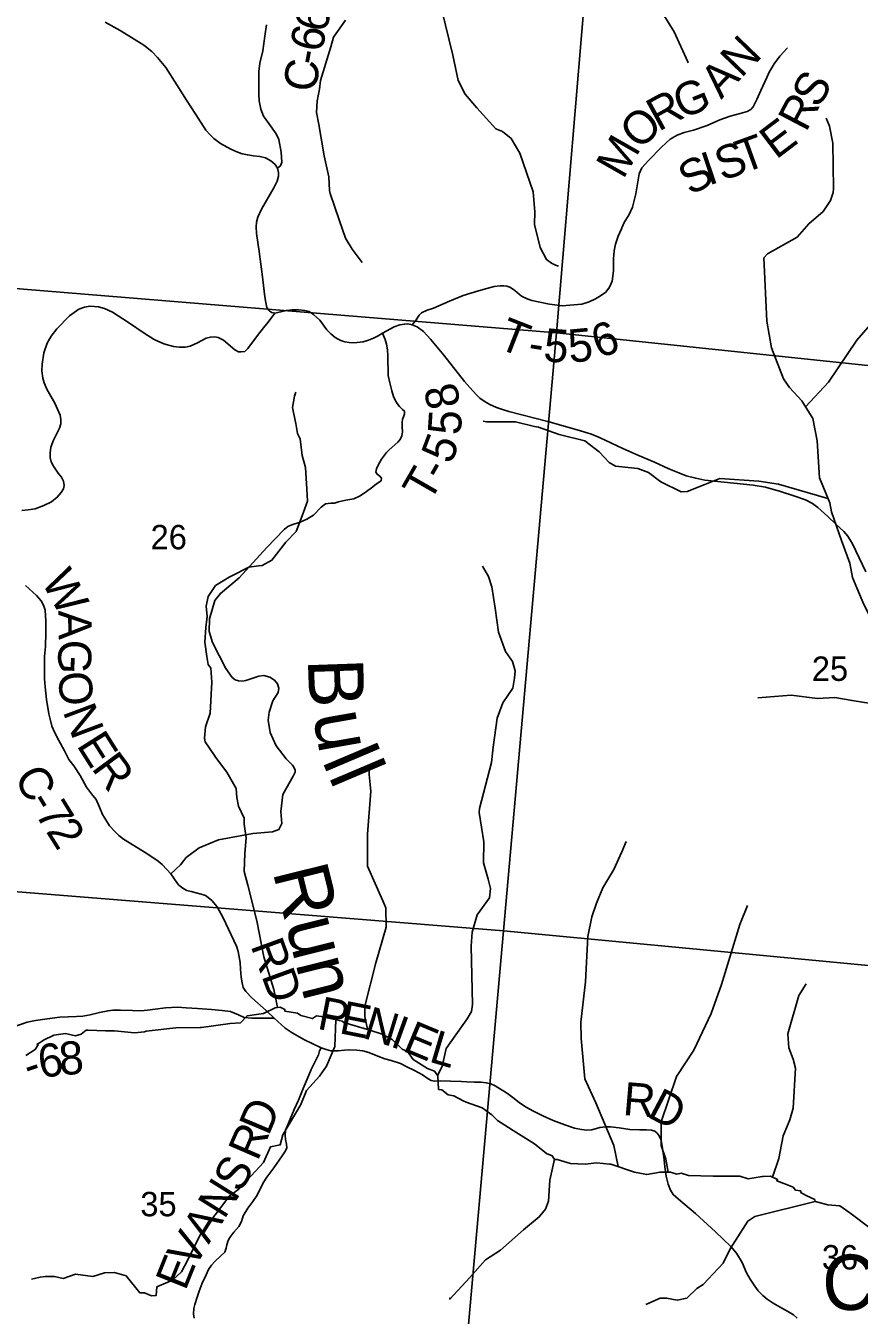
# Model space of a CAD drawing. Extents: x 1878108 to 2183446, y 146837 to 508383.
# Drawn here: x 1969519 to 1977068, y 283114 to 294796 of the extents above; entities that cross this region are included whole.
import ezdxf

# ---------------------------------------------------------------- set-up
doc = ezdxf.new("R2010")
doc.units = 0
for name, color, linetype in [('GM_X_County_Road', 7, 'Continuous'), ('GM_X_County_Road_Text', 7, 'Continuous'), ('GM_X_Minor_River', 7, 'Continuous'), ('GM_X_Minor_River_Text', 7, 'Continuous'), ('GM_X_Section', 7, 'Continuous'), ('GM_X_Section_Text', 7, 'Continuous'), ('GM_X_State_Route', 7, 'Continuous'), ('GM_X_Township_Road', 7, 'Continuous'), ('GM_X_Township_Road_Text', 7, 'Continuous'), ('GM_X_Township_ROW', 7, 'Continuous')]:
    doc.layers.add(name, color=color, linetype=linetype)

msp = doc.modelspace()

# ---------------------------------------------------------------- linework, layer by layer
at = {"layer": 'GM_X_County_Road'}
for points in [[(1971799, 293506), (1971825, 293529), (1971839, 293562), (1971832, 293651), (1971810, 293766), (1971787, 293817), (1971721, 293912), (1971672, 293979), (1971648, 294042), (1971633, 294115), (1971630, 294173), (1971629, 294275), (1971630, 294383), (1971639, 294459), (1971665, 294569), (1971684, 294701), (1971700, 294804)], [(1969483, 290405), (1969539, 290410), (1969603, 290420), (1969683, 290449), (1969750, 290483), (1969804, 290525), (1969840, 290567), (1969859, 290601), (1969865, 290632), (1969860, 290671), (1969841, 290708), (1969813, 290744), (1969769, 290806), (1969749, 290845), (1969739, 290885), (1969738, 290928), (1969744, 290978), (1969770, 291041), (1969824, 291152), (1969836, 291190), (1969837, 291230), (1969830, 291270), (1969782, 291377), (1969710, 291503), (1969686, 291561), (1969674, 291605), (1969665, 291669), (1969666, 291731), (1969681, 291834), (1969712, 291920), (1969747, 291984), (1969799, 292051), (1969915, 292168), (1969999, 292228), (1970050, 292247), (1970100, 292255), (1970178, 292249), (1970232, 292234), (1970305, 292202), (1970448, 292108), (1970591, 292010), (1970680, 291955), (1970770, 291914), (1970858, 291890), (1970910, 291884), (1970966, 291885), (1971008, 291895), (1971075, 291925), (1971154, 291965), (1971191, 291976), (1971231, 291979), (1971262, 291973), (1971309, 291948), (1971411, 291861), (1971445, 291843), (1971470, 291841), (1971502, 291846), (1971531, 291872), (1971618, 291991), (1971673, 292061), (1971715, 292110), (1971775, 292194)], [(1971769, 285804), (1971697, 285875), (1971565, 285990), (1971512, 286047), (1971488, 286084), (1971478, 286125), (1971469, 286176), (1971465, 286249), (1971459, 286310), (1971447, 286376), (1971442, 286409), (1971426, 286457), (1971306, 286715), (1971251, 286814), (1971203, 286870), (1971172, 286899), (1971147, 286917), (1971108, 286928), (1971016, 286952), (1970978, 286962), (1970950, 286978), (1970930, 286992), (1970905, 287009), (1970892, 287025), (1970859, 287074), (1970831, 287112), (1970795, 287153), (1970754, 287196), (1970717, 287227), (1970615, 287297), (1970404, 287426), (1970360, 287460), (1970324, 287497), (1970278, 287549), (1970243, 287602), (1970213, 287650), (1970186, 287716), (1970156, 287786), (1970114, 287837), (1970069, 287899), (1970010, 288004), (1969955, 288092), (1969909, 288149), (1969865, 288232), (1969819, 288320), (1969782, 288389), (1969753, 288452), (1969742, 288501), (1969728, 288563), (1969707, 288692), (1969694, 288807), (1969688, 288879), (1969689, 289000), (1969689, 289083), (1969696, 289173), (1969701, 289297), (1969700, 289403), (1969694, 289501), (1969679, 289546), (1969658, 289587), (1969615, 289634), (1969515, 289725)], [(1969410, 285726), (1969530, 285768), (1969607, 285784), (1969713, 285800), (1969826, 285813), (1969977, 285821), (1970035, 285823), (1970102, 285836), (1970185, 285856), (1970264, 285873), (1970308, 285877), (1970376, 285878), (1970484, 285875), (1970561, 285873), (1970622, 285877), (1970691, 285886), (1970785, 285900), (1970892, 285905), (1970971, 285900), (1971073, 285894), (1971202, 285884), (1971298, 285876), (1971373, 285864), (1971445, 285835), (1971497, 285812), (1971567, 285805), (1971640, 285804), (1971769, 285804), (1971869, 285715), (1971933, 285671), (1972042, 285610), (1972194, 285536), (1972239, 285521), (1972282, 285510), (1972317, 285508), (1972349, 285509), (1972406, 285516), (1972453, 285518), (1972518, 285515), (1972572, 285508), (1972625, 285493), (1972707, 285461), (1972771, 285437), (1972827, 285422), (1972912, 285394), (1972975, 285361), (1973034, 285335), (1973079, 285310), (1973112, 285292), (1973164, 285255), (1973192, 285240), (1973220, 285234), (1973274, 285236), (1973365, 285234), (1973465, 285230), (1973513, 285228), (1973582, 285225), (1973645, 285224), (1973689, 285220), (1973730, 285211), (1973769, 285192), (1973818, 285162), (1973850, 285144), (1973882, 285122), (1973932, 285085), (1973988, 285040), (1974037, 285007), (1974072, 284986), (1974124, 284959), (1974202, 284919), (1974295, 284879), (1974402, 284839), (1974490, 284808), (1974553, 284795), (1974602, 284791), (1974647, 284794), (1974720, 284813), (1974773, 284822), (1974814, 284821), (1974893, 284812), (1974990, 284797), (1975079, 284792), (1975142, 284792), (1975188, 284791), (1975216, 284781), (1975239, 284763), (1975256, 284739), (1975273, 284700), (1975287, 284623), (1975300, 284521), (1975308, 284459), (1975319, 284375), (1975338, 284300), (1975359, 284248), (1975382, 284207), (1975431, 284165), (1975586, 284036), (1975767, 283870), (1975905, 283735), (1975958, 283675), (1976009, 283590), (1976048, 283497), (1976081, 283439), (1976124, 283376), (1976153, 283336), (1976195, 283292), (1976233, 283259), (1976288, 283223), (1976373, 283175), (1976429, 283145), (1976474, 283116), (1976506, 283086)]]:
    msp.add_lwpolyline(points, dxfattribs=at)
at = {"layer": 'GM_X_Minor_River'}
for points in [[(1973941, 296117), (1974021, 296095), (1974173, 295826), (1974252, 295750), (1974320, 295711), (1974458, 295677), (1974544, 295619), (1974697, 295565), (1974867, 295436), (1975097, 295218), (1975140, 295140), (1975208, 295065), (1975251, 294970), (1975392, 294741), (1975516, 294469), (1975519, 294460)], [(1973407, 295607), (1973332, 295485), (1973288, 295100), (1973288, 294937), (1973387, 294530), (1973434, 294301), (1973500, 294176), (1973604, 294053), (1973775, 293862), (1973836, 293838), (1973916, 293774), (1973993, 293642), (1974114, 293292), (1974130, 293112), (1974128, 292997), (1974178, 292787), (1974235, 292678), (1974281, 292645), (1974316, 292629), (1974345, 292617)], [(1972415, 294847), (1972305, 294693), (1972281, 294605), (1972188, 294301), (1972180, 294221), (1972157, 294117), (1972153, 294011), (1972173, 293901), (1972220, 293619), (1972265, 293429), (1972269, 293305), (1972275, 293277), (1972356, 293039), (1972414, 292871), (1972476, 292773), (1972567, 292652)], [(1976801, 290473), (1976707, 290702), (1976688, 291037), (1976649, 291239), (1976548, 291399), (1976437, 291519), (1976381, 291597), (1976275, 291880), (1976231, 292120), (1976204, 292693), (1976237, 292729), (1976505, 292882), (1976611, 293003), (1976741, 293113), (1976808, 293213), (1976831, 293286), (1976834, 293322), (1976830, 293734), (1976798, 293887), (1976769, 293958)], [(1976583, 291344), (1976790, 291569), (1977047, 291948), (1977510, 292481), (1977735, 292689), (1977832, 292755)], [(1971798, 285902), (1971766, 286064), (1971674, 286360), (1971611, 286688), (1971530, 287010), (1971497, 287134), (1971503, 287296), (1971514, 287440), (1971496, 287562), (1971498, 287618), (1971444, 287726), (1971431, 287803), (1971425, 287887), (1971341, 288035), (1971238, 288171), (1971228, 288185), (1971142, 288309), (1971138, 288343), (1971147, 288445), (1971189, 288569), (1971204, 288849), (1971194, 288977), (1971170, 289009), (1971160, 289081), (1971141, 289213), (1971149, 289345), (1971163, 289445), (1971152, 289539), (1971172, 289627), (1971236, 289725), (1971360, 289801), (1971386, 289814), (1971540, 289890), (1971628, 289904), (1971660, 289906), (1971748, 289954), (1971875, 290118), (1971969, 290215), (1972021, 290355), (1972070, 290489), (1972064, 290599), (1972052, 290795), (1972023, 290903), (1972005, 291055), (1971981, 291101), (1971966, 291193), (1971960, 291219), (1971934, 291337), (1971954, 291441), (1971964, 291477)], [(1976784, 290514), (1976337, 290643), (1976160, 290671), (1975807, 290695), (1975670, 290640), (1975511, 290576), (1975455, 290574), (1975272, 290663), (1975159, 290749), (1975063, 290784), (1974860, 290806), (1974802, 290840), (1974714, 290936), (1974582, 291036), (1974351, 291092), (1974163, 291161), (1974127, 291167), (1973955, 291207), (1973694, 291207), (1973663, 291215)], [(1977666, 288655), (1977628, 288681), (1977620, 288721), (1977571, 288822), (1977567, 288868), (1977473, 289012), (1977465, 289036), (1977362, 289156), (1977342, 289162), (1977290, 289244), (1977212, 289354), (1977109, 289552), (1977008, 289797), (1976984, 289929), (1976909, 290133), (1976818, 290393), (1976801, 290473)], [(1973247, 285287), (1973289, 285367), (1973326, 285531), (1973517, 285800), (1973556, 285867), (1973566, 285929), (1973552, 286457), (1973563, 286585), (1973608, 286741), (1973719, 286894), (1973728, 286980), (1973708, 287066), (1973666, 287211), (1973667, 287402), (1973627, 287670), (1973629, 287706), (1973738, 288123), (1973752, 288259), (1973788, 288524), (1973841, 288661), (1973929, 288794), (1973947, 288887), (1973952, 288951), (1973927, 289037), (1973863, 289128), (1973801, 289301), (1973770, 289521), (1973741, 289712), (1973711, 289806), (1973657, 289900)], [(1977627, 288684), (1977500, 288671), (1977344, 288628), (1977003, 288683), (1976846, 288710), (1976689, 288702), (1976452, 288731), (1976149, 288707)], [(1972613, 285704), (1972590, 285820), (1972591, 285915), (1972690, 286306), (1972784, 286630), (1972780, 286805), (1972754, 286867), (1972615, 287182), (1972615, 287472), (1972644, 287862), (1972628, 288014), (1972629, 288050)], [(1974884, 284461), (1974845, 284651), (1974682, 285038), (1974583, 285256), (1974549, 285621), (1974547, 285768), (1974588, 286133), (1974611, 286545), (1974645, 286722), (1974687, 286846), (1974745, 286987), (1974845, 287153), (1974918, 287313), (1974957, 287405)], [(1975337, 284410), (1975316, 284527), (1975275, 284650), (1975273, 284867), (1975412, 285276), (1975569, 285515), (1975728, 285846), (1975820, 286109), (1975988, 286655), (1976056, 286825)], [(1976284, 284364), (1976341, 284533), (1976379, 284738), (1976440, 284884), (1976471, 284991), (1976492, 285353), (1976469, 285435), (1976432, 285536), (1976421, 285664), (1976521, 286011), (1976588, 286117)], [(1976668, 284145), (1976666, 284161), (1976593, 284196), (1976541, 284222), (1976535, 284242), (1976491, 284248), (1976469, 284274), (1976409, 284298), (1976321, 284332), (1976329, 284342), (1976265, 284374), (1976201, 284372), (1976189, 284370), (1976061, 284349), (1975988, 284373), (1975746, 284375), (1975522, 284379), (1975456, 284402), (1975416, 284392), (1975358, 284410), (1975264, 284410), (1975144, 284388), (1975034, 284410), (1974819, 284481), (1974805, 284481), (1974691, 284495), (1974587, 284481), (1974453, 284487), (1974331, 284526), (1974309, 284526), (1974287, 284558), (1974235, 284578), (1974126, 284668), (1973934, 284788), (1973890, 284814), (1973791, 284877), (1973741, 284929), (1973653, 284993), (1973509, 285043), (1973481, 285055), (1973396, 285101), (1973346, 285111), (1973288, 285155), (1973258, 285159), (1973250, 285283), (1973222, 285325), (1973156, 285350), (1973029, 285430), (1972975, 285504), (1972929, 285524), (1972837, 285612), (1972748, 285660), (1972634, 285695), (1972400, 285767), (1972384, 285777), (1972195, 285821), (1972153, 285827), (1972115, 285801), (1972009, 285830), (1971979, 285850), (1971865, 285870), (1971865, 285884), (1971823, 285906), (1971777, 285898), (1971671, 285848)], [(1972328, 285790), (1972319, 285547), (1972242, 285370), (1972178, 285281), (1972060, 285149), (1972010, 285024), (1971846, 284747), (1971824, 284658), (1971736, 284640), (1971672, 284497), (1971447, 284257), (1971362, 284193), (1971322, 284137), (1971106, 283856), (1970957, 283559), (1970930, 283508), (1970848, 283430), (1970707, 283371), (1970700, 283293), (1970656, 283288), (1970595, 283318), (1970551, 283317), (1970427, 283470), (1970322, 283500), (1970232, 283498), (1970127, 283465), (1969968, 283487), (1969857, 283447), (1969778, 283466), (1969693, 283464), (1969649, 283459), (1969571, 283440)], [(1971671, 285848), (1971523, 285826), (1971463, 285763), (1971369, 285757), (1971111, 285721), (1971099, 285721), (1970879, 285718), (1970609, 285688)], [(1970084, 285695), (1970066, 285695), (1970020, 285659), (1969970, 285645), (1969878, 285667), (1969774, 285652), (1969680, 285606), (1969666, 285596), (1969620, 285566), (1969630, 285564), (1969604, 285522), (1969518, 285468)], [(1970242, 285690), (1970083, 285695)], [(1970503, 285673), (1970322, 285689), (1970242, 285690)], [(1970609, 285688), (1970595, 285682), (1970503, 285673)], [(1974308, 284527), (1974265, 284337), (1974254, 284147), (1974225, 284074), (1974170, 284005), (1974027, 283888), (1973818, 283702), (1973683, 283616), (1973540, 283455), (1973361, 283258), (1973364, 283275)], [(1976668, 284145), (1976123, 284009), (1976059, 283967), (1975900, 283715), (1975836, 283586), (1975654, 283391), (1975596, 283357), (1975507, 283267), (1975418, 283251), (1975323, 283269), (1975266, 283267), (1975136, 283210)], [(1976668, 284145), (1976680, 284141)], [(1978740, 283050), (1978656, 283154), (1978539, 283288), (1978531, 283326), (1978399, 283482), (1978359, 283504), (1978156, 283621), (1978050, 283685), (1977936, 283709), (1977898, 283721), (1977740, 283708), (1977584, 283664), (1977488, 283666), (1977373, 283750), (1977361, 283760), (1977181, 283893), (1976984, 284041), (1976892, 284105), (1976784, 284115), (1976680, 284141)]]:
    msp.add_lwpolyline(points, dxfattribs=at)
at = {"layer": 'GM_X_Section'}
for points in [[(1974785, 297478), (1974325, 292014), (1968793, 292466), (1969319, 297968)], [(1980230, 296976), (1979776, 291612), (1979764, 291444), (1974325, 292014), (1974785, 297478)], [(1968793, 292466), (1974325, 292014), (1973846, 286597), (1968353, 287038)], [(1974325, 292014), (1979764, 291444), (1979322, 286217), (1979310, 286077), (1973846, 286597)], [(1968353, 287038), (1973846, 286597), (1973374, 281296), (1973174, 281310), (1967876, 281762)], [(1979310, 286077), (1978813, 280841), (1973374, 281296), (1973846, 286597)]]:
    msp.add_lwpolyline(points, close=True, dxfattribs=at)
at = {"layer": 'GM_X_State_Route'}
msp.add_lwpolyline([(1970238, 294830), (1970372, 294753), (1970477, 294691), (1970589, 294621), (1970659, 294563), (1970712, 294510), (1970788, 294418), (1970888, 294261), (1970975, 294124), (1971059, 293993), (1971150, 293852), (1971188, 293807), (1971222, 293775), (1971282, 293731), (1971375, 293678), (1971429, 293654), (1971479, 293637), (1971529, 293626), (1971582, 293617), (1971639, 293611), (1971689, 293600), (1971738, 293574), (1971779, 293539), (1971799, 293506), (1971809, 293467), (1971809, 293434), (1971796, 293390), (1971765, 293329), (1971655, 293134), (1971621, 293061), (1971609, 293016), (1971604, 292974), (1971608, 292914), (1971633, 292750), (1971648, 292637), (1971661, 292547), (1971683, 292340), (1971692, 292289), (1971701, 292245), (1971723, 292216), (1971744, 292200), (1971775, 292194), (1971801, 292198), (1971879, 292218), (1971933, 292223), (1971991, 292223), (1972042, 292218), (1972087, 292207), (1972126, 292182), (1972182, 292128), (1972247, 292043), (1972281, 292005), (1972320, 291973), (1972349, 291957), (1972371, 291946), (1972410, 291932), (1972448, 291926), (1972491, 291925), (1972520, 291926), (1972574, 291934), (1972624, 291948), (1972669, 291967), (1972711, 291988), (1972751, 292010), (1972856, 292068), (1972908, 292087), (1972949, 292094), (1972979, 292095), (1973019, 292088), (1973063, 292069), (1973122, 292028), (1973186, 291956), (1973305, 291811), (1973494, 291574), (1973568, 291488), (1973603, 291450), (1973633, 291423), (1973680, 291390), (1973723, 291364), (1973784, 291338), (1973829, 291323), (1973895, 291303), (1974248, 291210), (1974513, 291135), (1974643, 291096), (1974722, 291063), (1974927, 290966), (1975064, 290906), (1975215, 290842), (1975345, 290783), (1975433, 290746), (1975502, 290719), (1975587, 290697), (1975670, 290681), (1976108, 290633), (1976219, 290616), (1976355, 290578), (1976475, 290539), (1976583, 290501), (1976646, 290467), (1976694, 290431), (1976784, 290351), (1976855, 290282), (1976928, 290214), (1976966, 290171), (1977008, 290102), (1977068, 289976), (1977128, 289848)], dxfattribs=at)
at = {"layer": 'GM_X_Township_Road'}
for points in [[(1974919, 292967), (1974942, 293020), (1974981, 293082), (1975014, 293154), (1975045, 293275), (1975076, 293455), (1975100, 293510), (1975159, 293575), (1975277, 293698), (1975357, 293768), (1975420, 293805), (1975483, 293831), (1975567, 293850), (1975692, 293893), (1975806, 293945), (1975899, 293979), (1975990, 294003), (1976052, 294021), (1976086, 294038), (1976108, 294062), (1976141, 294129), (1976177, 294211), (1976230, 294329), (1976254, 294375), (1976299, 294452), (1976348, 294520), (1976418, 294598)], [(1973019, 292088), (1973050, 292124), (1973082, 292174), (1973102, 292195), (1973153, 292219), (1973213, 292239), (1973358, 292302), (1973482, 292353), (1973618, 292395), (1973695, 292417), (1973760, 292433), (1973815, 292439), (1973848, 292440), (1973877, 292437), (1973903, 292428), (1973938, 292408), (1973967, 292383), (1974008, 292347), (1974059, 292322), (1974104, 292306), (1974176, 292292), (1974263, 292275), (1974380, 292260), (1974447, 292264), (1974555, 292275), (1974621, 292294), (1974679, 292322), (1974726, 292349), (1974774, 292384), (1974806, 292428), (1974830, 292482), (1974843, 292575), (1974842, 292684), (1974849, 292757), (1974860, 292817), (1974885, 292890), (1974914, 292956), (1974919, 292967)], [(1972715, 290724), (1972701, 290733), (1972690, 290752), (1972694, 290782), (1972711, 290815), (1972742, 290870), (1972785, 290930), (1972810, 290954), (1972889, 291025), (1972911, 291049), (1972926, 291082), (1972932, 291119), (1972927, 291163), (1972929, 291203), (1972932, 291232), (1972940, 291254), (1972949, 291280), (1972948, 291305), (1972932, 291321), (1972905, 291348), (1972884, 291373), (1972868, 291398), (1972850, 291437), (1972834, 291489), (1972815, 291561), (1972802, 291628), (1972798, 291807), (1972795, 291860), (1972787, 291913), (1972773, 291955), (1972751, 292010)], [(1971043, 283088), (1971037, 283125), (1971042, 283176), (1971049, 283210), (1971071, 283277), (1971090, 283333), (1971117, 283403), (1971151, 283481), (1971175, 283528), (1971201, 283566), (1971232, 283600), (1971286, 283651), (1971321, 283684), (1971333, 283721), (1971339, 283751), (1971353, 283790), (1971366, 283817), (1971403, 283867), (1971449, 283918), (1971474, 283963), (1971487, 284014), (1971531, 284085), (1971576, 284144), (1971614, 284201), (1971670, 284313), (1971701, 284363), (1971764, 284449), (1971842, 284557), (1971872, 284603), (1971882, 284630), (1971881, 284663), (1971871, 284706), (1971867, 284743), (1971871, 284790), (1971899, 284853), (1971951, 284977), (1971988, 285063), (1972032, 285168), (1972067, 285252), (1972104, 285340), (1972144, 285419), (1972170, 285472), (1972180, 285508), (1972194, 285536)]]:
    msp.add_lwpolyline(points, dxfattribs=at)
at = {"layer": 'GM_X_Township_ROW'}
msp.add_lwpolyline([(1970831, 287112), (1970920, 287195), (1970971, 287260), (1971089, 287348), (1971264, 287420), (1971574, 287477), (1971754, 287493), (1971811, 287513), (1971837, 287570), (1971828, 287677), (1971847, 287831), (1971942, 287999), (1971958, 288034), (1971960, 288053), (1971947, 288080), (1971934, 288096), (1971877, 288154), (1971787, 288274), (1971732, 288393), (1971714, 288506), (1971724, 288579), (1971757, 288679), (1971805, 288757), (1971810, 288796), (1971800, 288834), (1971773, 288869), (1971729, 288896), (1971675, 288909), (1971629, 288904), (1971511, 288865), (1971479, 288859), (1971445, 288861), (1971414, 288872), (1971388, 288892), (1971332, 288972), (1971210, 289209), (1971181, 289309), (1971182, 289422), (1971231, 289588), (1971281, 289654), (1971450, 289795), (1971703, 290069), (1971859, 290234), (1971893, 290259), (1971930, 290275), (1972003, 290300), (1972065, 290327), (1972124, 290362), (1972193, 290434), (1972233, 290464), (1972281, 290471), (1972314, 290472), (1972352, 290483), (1972418, 290497), (1972491, 290509), (1972540, 290535), (1972594, 290567), (1972661, 290619), (1972695, 290646), (1972737, 290674), (1972742, 290697), (1972726, 290717), (1972715, 290724)], dxfattribs=at)

# ---------------------------------------------------------------- texts
at = {"layer": 'GM_X_County_Road_Text'}
for s, rotation, p in [('6', 76.9937, (1972238, 294726)), ('6', 78.0721, (1972200, 294547)), ('-', 79.529, (1972178, 294428)), ('C', 82.7486, (1972148, 294188)), ('W', 298.7407, (1969654, 289767)), ('A', 271.3042, (1969812, 289499)), ('G', 267.8831, (1969818, 289239)), ('O', 274.9014, (1969809, 288935)), ('N', 290.569, (1969851, 288585)), ('E', 302.2445, (1969973, 288278)), ('R', 306.4966, (1970107, 288069)), ('C', 299.4184, (1969406, 287990)), ('-', 301.4488, (1969533, 287766)), ('7', 301.5122, (1969597, 287660)), ('2', 302.1592, (1969696, 287499)), ('RD', 290.0262, (1971552, 286463)), ('P', 348.7963, (1972150, 285710)), ('E', 348.6943, (1972348, 285671)), ('N', 342.9757, (1972561, 285629)), ('I', 340.1036, (1972809, 285553)), ('E', 337.3526, (1972922, 285512)), ('L', 343.518, (1973161, 285414)), ('6', 8.656, (1969653, 285260)), ('8', 4.4173, (1969830, 285287)), ('-', 18.5599, (1969550, 285224)), ('R', 355.131, (1974921, 284929)), ('D', 332.2318, (1975137, 284917))]:
    msp.add_text(s, height=300, rotation=rotation, dxfattribs=at).set_placement(p)
at = {"layer": 'GM_X_Minor_River_Text'}
for s, rotation, p in [('B', 272.0001, (1972073, 289058)), ('u', 280, (1972119, 288553)), ('ll', 292.9995, (1972200, 288137)), ('Run', 283.9995, (1971753, 287134)), ('Creek', 0.1018, (1976733, 283161))]:
    msp.add_text(s, height=500, rotation=rotation, dxfattribs=at).set_placement(p)
at = {"layer": 'GM_X_Section_Text'}
for s, p in [('26', (1970649, 290053)), ('25', (1976639, 288861)), ('35', (1970556, 284010)), ('36', (1976730, 283528))]:
    msp.add_text(s, height=221, rotation=0, dxfattribs=at).set_placement(p)
at = {"layer": 'GM_X_Township_Road_Text'}
for s, rotation, p in [('N', 46.0407, (1976000, 294316)), ('A', 46.3851, (1975818, 294125)), ('G', 21.9448, (1975459, 293948)), ('S', 59.931, (1976699, 294040)), ('R', 28.7587, (1975251, 293834)), ('R', 62.3848, (1976586, 293825)), ('O', 43.9593, (1975078, 293663)), ('E', 37.1656, (1976315, 293580)), ('M', 60.291, (1974931, 293398)), ('S', 19.4844, (1975825, 293388)), ('T', 19.9665, (1976018, 293457)), ('S', 30.1191, (1975542, 293252)), ('I', 18.5004, (1975703, 293347)), ('T', 338.61, (1973780, 291881)), ('6', 20.237, (1974711, 291779)), ('5', 355.0376, (1974201, 291759)), ('5', 5.465, (1974445, 291743)), ('-', 351.1613, (1974058, 291780)), ('8', 103.3782, (1973462, 291364)), ('5', 86.3348, (1973458, 291083)), ('5', 69.2287, (1973372, 290815)), ('T', 60.1116, (1973177, 290466)), ('-', 60.4026, (1973290, 290662)), ('D', 67.1575, (1971717, 284731)), ('R', 66.6351, (1971618, 284502)), ('S', 60.9783, (1971465, 284214)), ('N', 57.9679, (1971316, 283975)), ('A', 57.8266, (1971175, 283751)), ('V', 59.4126, (1971042, 283525)), ('E', 68.2014, (1970964, 283328))]:
    msp.add_text(s, height=300, rotation=rotation, dxfattribs=at).set_placement(p)

doc.saveas('drawing.dxf')
